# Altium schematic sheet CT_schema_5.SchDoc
size 278 x 236 mm
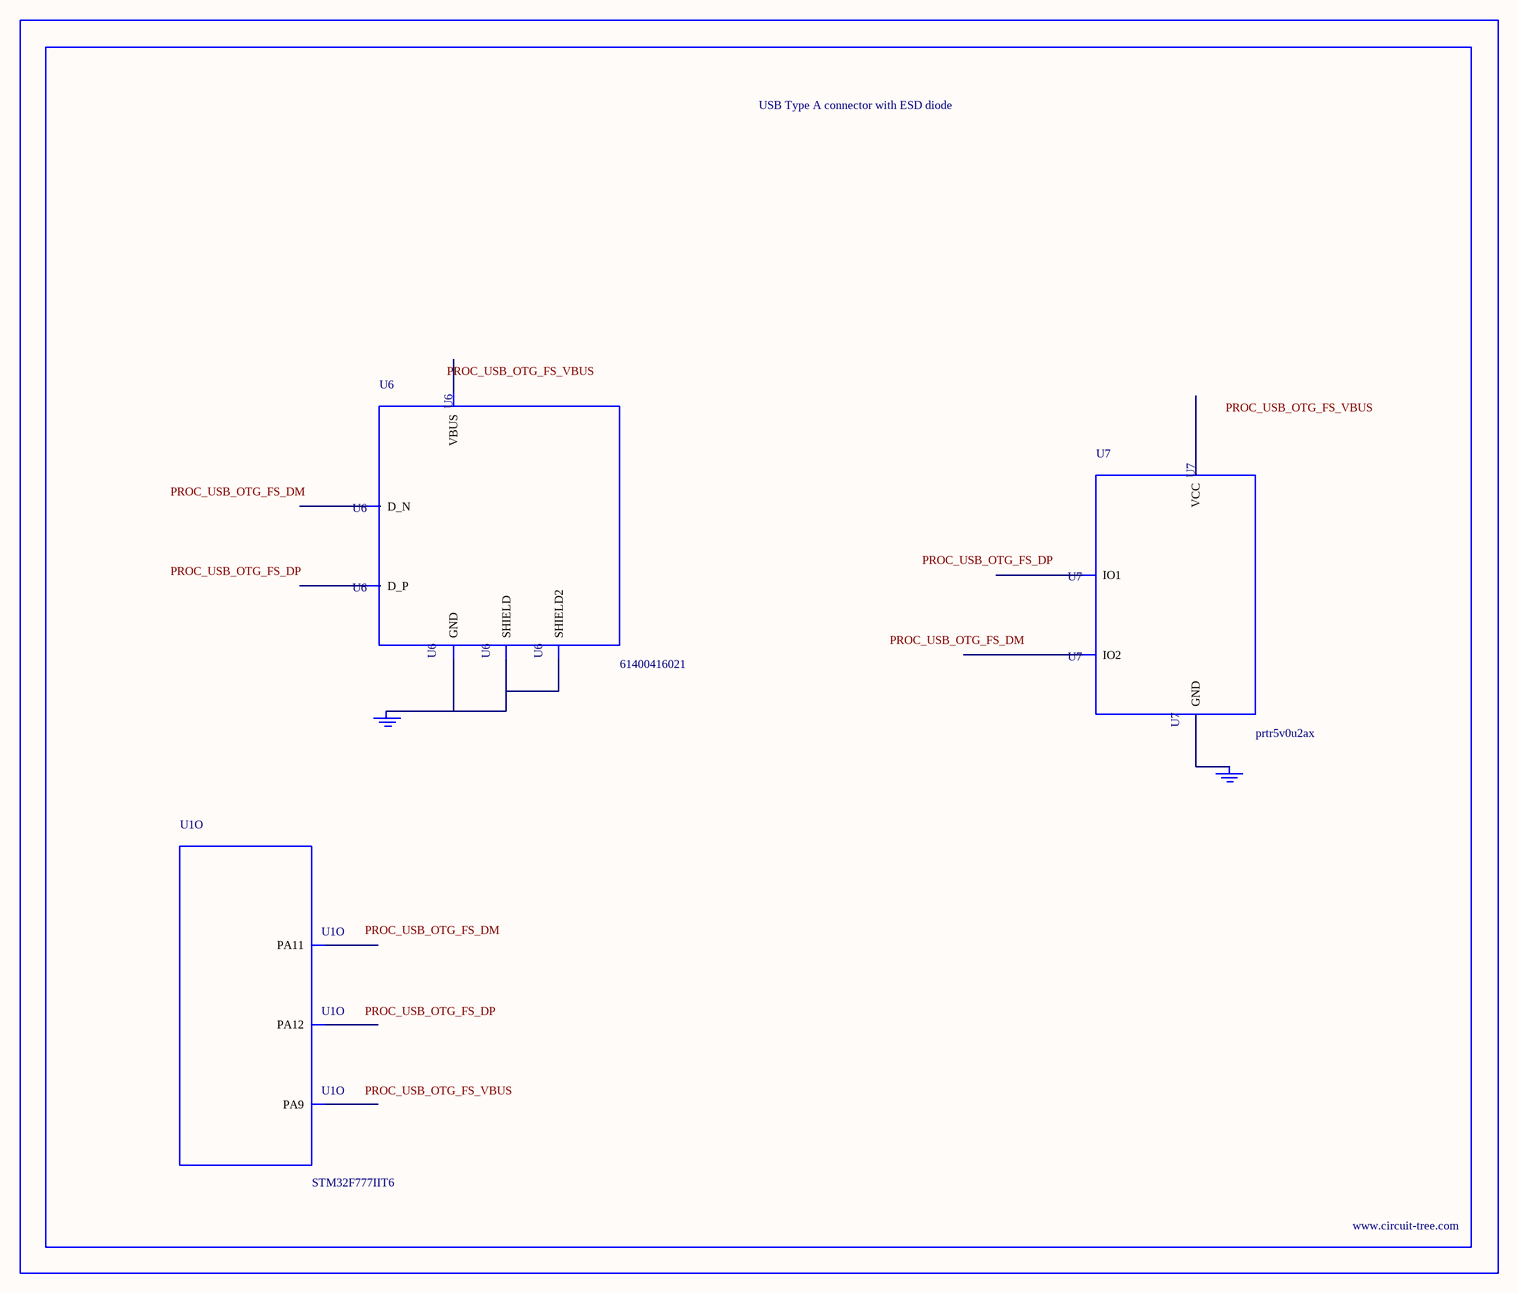
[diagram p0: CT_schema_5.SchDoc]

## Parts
BORDER4  (no value)
GND_INSTANCE_4_0  (no value)
GND_INSTANCE_4_1  (no value)
U1  STM32F777IIT6  [LQFP176]  (part O of 15)
U6  61400416021  [USB-A-H]
U7  prtr5v0u2ax  [SOT143B]

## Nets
NetGND_INSTANCE_4_0_0: GND_INSTANCE_4_0.0(GND) U6.4(GND) U6.5(SHIELD) U6.6(SHIELD2)
NetGND_INSTANCE_4_1_0: GND_INSTANCE_4_1.0(GND) U7.1(GND)

Not connected (* = marked no-connect by the designer): U1 120(PA9) 122(PA11) 123(PA12); U6 1(VBUS) 2(D_N) 3(D_P); U7 2(IO1) 3(IO2) 4(VCC)

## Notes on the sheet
- Labels drawn without touching a wire or pin: PROC_USB_OTG_FS_DM, PROC_USB_OTG_FS_DP, PROC_USB_OTG_FS_VBUS

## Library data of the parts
BORDER4 = BORDER_PAGE4
GND_INSTANCE_4_0 GND_INSTANCE_4_1 = GND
